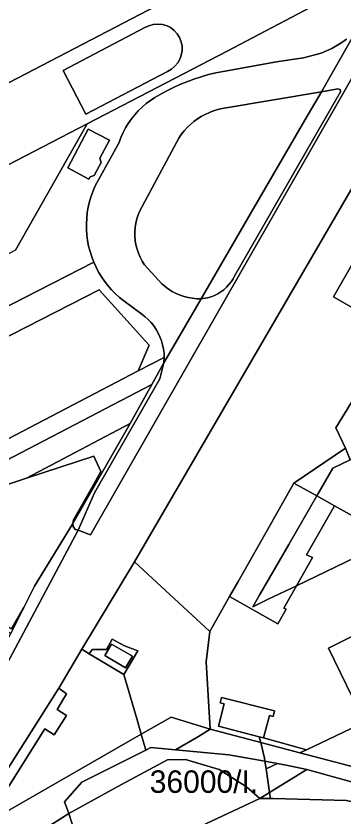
# Model space of a CAD drawing. Extents: x -537068 to -534056, y -1176840 to -1172401.
# Drawn here: x -536084.1 to -536011, y -1175324.5 to -1175146.2 of the extents above; entities that cross this region are included whole.
import ezdxf

# ---------------------------------------------------------------- set-up
doc = ezdxf.new("R2010")
doc.units = 0
for name, color, linetype in [('95560013', 7, 'Continuous'), ('95590013', 7, 'Continuous'), ('95630013', 7, 'Continuous'), ('95640013', 7, 'Continuous'), ('95660013', 7, 'Continuous')]:
    doc.layers.add(name, color=color, linetype=linetype)

msp = doc.modelspace()

# ---------------------------------------------------------------- linework, layer by layer
at = {"layer": '95560013'}
for points in [[(-536054.62, -1175144.91), (-536125.64, -1175181.74), (-536189.92, -1175215.07), (-536156.5, -1175178.11), (-536127.83, -1175145.22), (-536061.58, -1175110.73), (-535994.48, -1175074.73), (-535960.11, -1175056.29), (-535953.43, -1175065.31), (-535960.73, -1175075.89), (-535971.74, -1175091.4), (-535983.6, -1175108.09)], [(-536178.93, -1175228.66), (-536210.17, -1175250.41), (-536219.68, -1175249.12), (-536204.88, -1175232.04), (-536189.92, -1175215.07), (-536125.64, -1175181.74), (-536054.62, -1175144.91), (-535983.6, -1175108.09), (-535999.49, -1175133.94), (-535999.76, -1175134.32), (-536037.06, -1175154.03), (-536068.2, -1175170.14), (-536103.53, -1175188.42)], [(-536050.43, -1175148.4), (-536051.48, -1175148.08), (-536052.53, -1175147.97), (-536053.55, -1175148.06), (-536054.52, -1175148.33), (-536055.42, -1175148.77), (-536073.61, -1175158.31), (-536068.5, -1175168.05), (-536050.34, -1175158.5), (-536049.47, -1175158.01), (-536048.69, -1175157.37), (-536048.03, -1175156.58), (-536047.52, -1175155.66), (-536047.19, -1175154.62), (-536047.09, -1175153.91), (-536047.1, -1175152.89), (-536047.3, -1175151.9), (-536047.67, -1175150.97), (-536048.2, -1175150.12), (-536048.89, -1175149.38), (-536049.71, -1175148.77)]]:
    msp.add_lwpolyline(points, close=True, dxfattribs=at)
at = {"layer": '95590013'}
for points in [[(-536084.19, -1175198.31), (-536068.2, -1175170.14), (-536037.06, -1175154.03), (-535999.76, -1175134.32)], [(-536010.49, -1175151.32), (-536011.55, -1175152.07), (-536012.64, -1175152.76), (-536013.78, -1175153.39), (-536014.94, -1175153.95), (-536016.14, -1175154.44), (-536020.08, -1175155.46), (-536026.06, -1175156.41), (-536037.95, -1175158.5), (-536039.6, -1175158.84), (-536041.24, -1175159.23), (-536042.86, -1175159.69), (-536044.47, -1175160.22), (-536046.05, -1175160.8), (-536047.61, -1175161.44), (-536049.15, -1175162.13), (-536050.65, -1175162.89), (-536052.13, -1175163.7), (-536053.16, -1175164.29), (-536054.15, -1175164.95), (-536055.1, -1175165.67), (-536056, -1175166.45), (-536056.85, -1175167.28), (-536057.65, -1175168.16), (-536058.39, -1175169.09), (-536059.07, -1175170.07), (-536059.69, -1175171.09), (-536060.24, -1175172.14), (-536060.72, -1175173.23), (-536061.14, -1175174.34), (-536066.42, -1175183.96), (-536066.92, -1175185.11), (-536067.35, -1175186.28), (-536067.7, -1175187.48), (-536067.99, -1175188.7), (-536068.2, -1175189.93), (-536068.34, -1175191.17), (-536068.4, -1175192.42), (-536068.39, -1175193.67), (-536068.3, -1175194.92), (-536068.14, -1175196.16), (-536067.91, -1175197.39), (-536067.6, -1175198.6), (-536067.22, -1175199.79), (-536066.77, -1175200.96), (-536100.61, -1175218.24)], [(-536100.61, -1175218.24), (-536066.77, -1175200.96), (-536066.26, -1175202.08), (-536065.69, -1175203.16), (-536065.05, -1175204.21), (-536064.36, -1175205.22), (-536063.6, -1175206.19), (-536062.79, -1175207.11), (-536061.93, -1175207.99), (-536061.02, -1175208.81), (-536060.06, -1175209.57), (-536056.07, -1175212.52), (-536055.33, -1175213.1), (-536054.64, -1175213.73), (-536053.99, -1175214.42), (-536053.41, -1175215.15), (-536052.88, -1175215.93), (-536052.42, -1175216.75), (-536052.02, -1175217.6), (-536051.69, -1175218.48), (-536051.43, -1175219.38), (-536051.24, -1175220.3), (-536051.12, -1175221.23), (-536051.08, -1175222.17), (-536056.87, -1175225.18), (-536054.45, -1175219.42), (-536055.23, -1175218.56), (-536065.59, -1175207.09), (-536098, -1175223.64)]]:
    msp.add_lwpolyline(points, dxfattribs=at)
for points in [[(-536051.6, -1175205.78), (-536055.47, -1175201.53), (-536055.99, -1175200.71), (-536056.44, -1175199.85), (-536056.82, -1175198.96), (-536057.13, -1175198.04), (-536057.36, -1175197.1), (-536057.52, -1175196.14), (-536057.6, -1175195.18), (-536057.61, -1175194.21), (-536057.53, -1175193.24), (-536057.38, -1175192.28), (-536057.16, -1175191.34), (-536056.85, -1175190.42), (-536056.48, -1175189.52), (-536047.84, -1175173.38), (-536047.27, -1175172.55), (-536046.65, -1175171.76), (-536045.97, -1175171.02), (-536045.25, -1175170.32), (-536044.48, -1175169.68), (-536043.67, -1175169.09), (-536042.82, -1175168.55), (-536041.94, -1175168.07), (-536041.02, -1175167.66), (-536040.08, -1175167.3), (-536039.12, -1175167.01), (-536038.14, -1175166.79), (-536016.03, -1175163.03), (-536019.73, -1175169.37), (-536031.7, -1175189.91), (-536042.87, -1175209.12), (-536043.83, -1175209.1), (-536044.78, -1175209.01), (-536045.73, -1175208.85), (-536046.65, -1175208.61), (-536047.56, -1175208.3), (-536048.44, -1175207.93), (-536049.29, -1175207.48), (-536050.1, -1175206.98), (-536050.88, -1175206.41)], [(-536084.19, -1175198.31), (-536104.99, -1175209.19), (-536164.36, -1175240.23), (-536192.84, -1175260.15), (-536195.67, -1175258.06), (-536205.32, -1175260.27), (-536214.58, -1175253.88), (-536210.17, -1175250.41), (-536178.93, -1175228.66), (-536103.53, -1175188.42), (-536068.2, -1175170.14)], [(-536067.86, -1175182.48), (-536067.59, -1175181.97), (-536066.67, -1175181.69), (-536065.12, -1175178.78), (-536065.41, -1175177.84), (-536063.28, -1175173.81), (-536067.98, -1175171.33), (-536072.56, -1175180)], [(-536096.17, -1175227.42), (-536098, -1175223.64), (-536065.59, -1175207.09), (-536055.23, -1175218.56), (-536054.45, -1175219.42), (-536056.87, -1175225.18), (-536089.15, -1175241.96), (-536091.37, -1175237.36), (-536093.77, -1175232.39)], [(-536051.08, -1175222.17), (-536051.13, -1175223.39), (-536053.84, -1175228.22), (-536086.44, -1175245.15), (-536100.79, -1175252.85), (-536124.04, -1175266.29), (-536137.58, -1175274.39), (-536150.6, -1175283.46), (-536154.77, -1175279.13), (-536124.94, -1175260.56), (-536089.15, -1175241.96), (-536056.87, -1175225.18)], [(-536095.46, -1175253.58), (-536097.74, -1175257.55), (-536117.45, -1175267.99), (-536147, -1175287.2), (-536150.6, -1175283.46), (-536137.58, -1175274.39), (-536124.04, -1175266.29), (-536100.79, -1175252.85), (-536086.44, -1175245.15), (-536053.84, -1175228.22), (-536058.69, -1175236.86), (-536081.73, -1175249.07)], [(-536081.73, -1175249.07), (-536058.69, -1175236.86), (-536066.56, -1175250.59), (-536067.07, -1175250.88), (-536065.21, -1175247.58), (-536066.72, -1175244.13)], [(-536067.07, -1175250.88), (-536066.56, -1175250.59), (-536071.45, -1175259.11), (-536071.27, -1175258.29)], [(-536051.03, -1175330.31), (-536052.39, -1175326.63), (-536069.36, -1175333.07), (-536070.72, -1175328.8), (-536072.32, -1175323.69), (-536060.56, -1175317.19), (-536050.36, -1175311.71), (-536046.36, -1175311.63), (-536038.85, -1175313.85), (-536032.73, -1175317.76), (-536029.77, -1175320.33)]]:
    msp.add_lwpolyline(points, close=True, dxfattribs=at)
at = {"layer": '95630013'}
for points in [[(-536056.18, -1175306.04), (-536049.5, -1175302.21), (-536040.85, -1175304.92), (-536043.42, -1175306.54), (-536048.56, -1175309.47), (-536054.03, -1175308.96), (-536055.2, -1175309.55)], [(-536028.73, -1175311.35), (-536028.63, -1175312.06), (-536036.71, -1175310.59), (-536048.56, -1175309.47), (-536043.42, -1175306.54), (-536040.85, -1175304.92), (-536029.59, -1175307.87)], [(-536073.25, -1175321.08), (-536072.32, -1175323.69), (-536082.9, -1175330.42), (-536089.72, -1175333.91), (-536093.25, -1175335.47), (-536096.47, -1175336.83), (-536098.11, -1175337.72), (-536096.43, -1175335), (-536093.75, -1175330.67), (-536092.69, -1175328.97), (-536090.76, -1175325.85), (-536056.18, -1175306.04), (-536055.2, -1175309.55), (-536069.41, -1175316.73)], [(-536028.39, -1175313.76), (-536027.63, -1175319.02), (-536029.77, -1175320.33), (-536032.73, -1175317.76), (-536038.85, -1175313.85), (-536046.36, -1175311.63), (-536050.36, -1175311.71), (-536060.56, -1175317.19), (-536072.32, -1175323.69), (-536073.25, -1175321.08), (-536069.41, -1175316.73), (-536055.2, -1175309.55), (-536054.03, -1175308.96), (-536048.56, -1175309.47), (-536036.71, -1175310.59), (-536028.63, -1175312.06)], [(-536029.77, -1175320.33), (-536027.63, -1175319.02), (-536027.44, -1175320.35)]]:
    msp.add_lwpolyline(points, close=True, dxfattribs=at)
at = {"layer": '95640013'}
for points in [[(-536006.58, -1175180), (-536057.72, -1175267.69), (-536069.4, -1175287.13), (-536074.57, -1175295.75), (-536092.07, -1175323.29), (-536092.88, -1175324.61), (-536095.32, -1175328.57), (-536096.89, -1175328.33), (-536105.95, -1175326.95), (-536107.53, -1175326.71), (-536108.93, -1175324.45), (-536106.79, -1175321.11), (-536105.14, -1175318.55), (-536092.78, -1175302.83), (-536070.22, -1175260.64), (-536067.46, -1175261.62), (-535997.55, -1175139.48)], [(-535997.55, -1175139.48), (-536067.46, -1175261.62), (-536070.22, -1175260.64), (-536066.61, -1175252.27), (-536052.02, -1175226.9), (-536051.13, -1175223.39), (-536050.19, -1175221.71), (-536046.27, -1175214.97), (-536042.87, -1175209.12), (-536041.42, -1175208.89), (-536040.64, -1175208.66), (-536039.88, -1175208.37), (-536039.16, -1175208.01), (-536038.46, -1175207.58), (-536037.81, -1175207.1), (-536037.2, -1175206.56), (-536036.65, -1175205.97), (-536036.15, -1175205.33), (-536035.7, -1175204.65), (-536035.32, -1175203.93), (-536011.78, -1175163.05), (-536011.91, -1175162.56), (-536012.39, -1175162.41), (-536016.03, -1175163.03), (-536015.73, -1175162.52), (-536008.33, -1175149.45)], [(-536008.33, -1175149.45), (-536015.73, -1175162.52), (-536016.03, -1175163.03), (-536038.14, -1175166.79), (-536039.12, -1175167.01), (-536040.08, -1175167.3), (-536041.02, -1175167.66), (-536041.94, -1175168.07), (-536042.82, -1175168.55), (-536043.67, -1175169.09), (-536044.48, -1175169.68), (-536045.25, -1175170.32), (-536045.97, -1175171.02), (-536046.65, -1175171.76), (-536047.27, -1175172.55), (-536047.84, -1175173.38), (-536056.48, -1175189.52), (-536056.85, -1175190.42), (-536057.16, -1175191.34), (-536057.38, -1175192.28), (-536057.53, -1175193.24), (-536057.61, -1175194.21), (-536057.6, -1175195.18), (-536057.52, -1175196.14), (-536057.36, -1175197.1), (-536057.13, -1175198.04), (-536056.82, -1175198.96), (-536056.44, -1175199.85), (-536055.99, -1175200.71), (-536055.47, -1175201.53), (-536051.6, -1175205.78), (-536050.88, -1175206.41), (-536050.1, -1175206.98), (-536049.29, -1175207.48), (-536048.44, -1175207.93), (-536047.56, -1175208.3), (-536046.65, -1175208.61), (-536045.73, -1175208.85), (-536044.78, -1175209.01), (-536043.83, -1175209.1), (-536042.87, -1175209.12), (-536046.27, -1175214.97), (-536050.19, -1175221.71), (-536051.13, -1175223.39), (-536051.08, -1175222.17), (-536051.12, -1175221.23), (-536051.24, -1175220.3), (-536051.43, -1175219.38), (-536051.69, -1175218.48), (-536052.02, -1175217.6), (-536052.42, -1175216.75), (-536052.88, -1175215.93), (-536053.41, -1175215.15), (-536053.99, -1175214.42), (-536054.64, -1175213.73), (-536055.33, -1175213.1), (-536056.07, -1175212.52), (-536060.06, -1175209.57), (-536061.02, -1175208.81), (-536061.93, -1175207.99), (-536062.79, -1175207.11), (-536063.6, -1175206.19), (-536064.36, -1175205.22), (-536065.05, -1175204.21), (-536065.69, -1175203.16), (-536066.26, -1175202.08), (-536066.77, -1175200.96), (-536067.22, -1175199.79), (-536067.6, -1175198.6), (-536067.91, -1175197.39), (-536068.14, -1175196.16), (-536068.3, -1175194.92), (-536068.39, -1175193.67), (-536068.4, -1175192.42), (-536068.34, -1175191.17), (-536068.2, -1175189.93), (-536067.99, -1175188.7), (-536067.7, -1175187.48), (-536067.35, -1175186.28), (-536066.92, -1175185.11), (-536066.42, -1175183.96), (-536061.14, -1175174.34), (-536060.72, -1175173.23), (-536060.24, -1175172.14), (-536059.69, -1175171.09), (-536059.07, -1175170.07), (-536058.39, -1175169.09), (-536057.65, -1175168.16), (-536056.85, -1175167.28), (-536056, -1175166.45), (-536055.1, -1175165.67), (-536054.15, -1175164.95), (-536053.16, -1175164.29), (-536052.13, -1175163.7), (-536050.65, -1175162.89), (-536049.15, -1175162.13), (-536047.61, -1175161.44), (-536046.05, -1175160.8), (-536044.47, -1175160.22), (-536042.86, -1175159.69), (-536041.24, -1175159.23), (-536039.6, -1175158.84), (-536037.95, -1175158.5), (-536026.06, -1175156.41), (-536020.08, -1175155.46), (-536016.14, -1175154.44), (-536014.94, -1175153.95), (-536013.78, -1175153.39), (-536012.64, -1175152.76), (-536011.55, -1175152.07), (-536010.49, -1175151.32)], [(-536003.42, -1175222.5), (-536012.83, -1175237.86), (-536010.73, -1175242.37), (-536022.18, -1175250.17), (-536028.36, -1175261.04), (-536034.68, -1175272.17), (-536036.5, -1175275.39), (-536040.89, -1175283.14), (-536057.72, -1175267.69), (-536006.58, -1175180)], [(-536003.09, -1175190.79), (-536013.4, -1175208.69), (-536006.52, -1175212.63)], [(-535960.29, -1175259.84), (-536014.5, -1175286.88), (-536006.45, -1175303.32), (-536019.38, -1175309.48), (-536028.93, -1175306.85), (-536027.66, -1175301.85), (-536026.79, -1175302.07), (-536026.48, -1175300.86), (-536038.33, -1175297.84), (-536038.63, -1175299.06), (-536037.76, -1175299.28), (-536038.99, -1175304.24), (-536029.9, -1175306.6), (-536029.59, -1175307.87), (-536040.85, -1175304.92), (-536041.7, -1175289.93), (-536040.89, -1175283.14), (-536036.5, -1175275.39), (-536025.76, -1175281.46), (-536023.94, -1175278.23), (-536024.46, -1175277.94), (-536021.64, -1175272.99), (-535999.92, -1175262.53)]]:
    msp.add_lwpolyline(points, dxfattribs=at)
for points in [[(-536073.61, -1175158.31), (-536055.42, -1175148.77), (-536054.52, -1175148.33), (-536053.55, -1175148.06), (-536052.53, -1175147.97), (-536051.48, -1175148.08), (-536050.43, -1175148.4), (-536049.71, -1175148.77), (-536048.89, -1175149.38), (-536048.2, -1175150.12), (-536047.67, -1175150.97), (-536047.3, -1175151.9), (-536047.1, -1175152.89), (-536047.09, -1175153.91), (-536047.19, -1175154.62), (-536047.52, -1175155.66), (-536048.03, -1175156.58), (-536048.69, -1175157.37), (-536049.47, -1175158.01), (-536050.34, -1175158.5), (-536068.5, -1175168.05)], [(-536031.7, -1175189.91), (-536019.73, -1175169.37), (-536016.03, -1175163.03), (-536012.39, -1175162.41), (-536011.91, -1175162.56), (-536011.78, -1175163.05), (-536035.32, -1175203.93), (-536035.7, -1175204.65), (-536036.15, -1175205.33), (-536036.65, -1175205.97), (-536037.2, -1175206.56), (-536037.81, -1175207.1), (-536038.46, -1175207.58), (-536039.16, -1175208.01), (-536039.88, -1175208.37), (-536040.64, -1175208.66), (-536041.42, -1175208.89), (-536042.87, -1175209.12)], [(-536065.12, -1175178.78), (-536066.67, -1175181.69), (-536067.59, -1175181.97), (-536067.86, -1175182.48), (-536072.56, -1175180), (-536067.98, -1175171.33), (-536063.28, -1175173.81), (-536065.41, -1175177.84)], [(-536003.09, -1175190.79), (-535996.3, -1175194.76), (-535994.52, -1175195.86), (-535991.02, -1175189.7), (-535978.79, -1175196.8), (-535970.96, -1175202.13), (-535968.03, -1175207.99), (-535964.85, -1175215.84), (-535961.82, -1175221.41), (-535963.9, -1175222.62), (-535992.6, -1175236.67), (-535994.16, -1175237.43), (-536005.74, -1175243.07), (-536009.65, -1175244.97), (-536010.73, -1175242.37), (-536012.83, -1175237.86), (-536003.42, -1175222.5), (-536004.88, -1175221.68), (-536004.08, -1175220.35), (-536007.44, -1175218.43), (-536004.74, -1175213.65), (-536006.52, -1175212.63), (-536013.4, -1175208.69)], [(-536071.32, -1175259.8), (-536071.45, -1175259.11), (-536066.56, -1175250.59), (-536058.69, -1175236.86), (-536053.84, -1175228.22), (-536051.13, -1175223.39), (-536052.02, -1175226.9), (-536066.61, -1175252.27), (-536070.22, -1175260.64), (-536070.88, -1175260.44)], [(-536022.18, -1175250.17), (-536010.73, -1175242.37), (-536009.65, -1175244.97), (-536013.49, -1175246.79), (-536017.08, -1175253)], [(-536003.46, -1175247.73), (-536004.27, -1175248.13), (-536003.73, -1175249.21), (-535991.44, -1175243.05), (-535985.32, -1175255.53), (-535982.41, -1175261.57), (-535992.56, -1175266.62), (-535999.92, -1175262.53), (-536013.12, -1175255.2), (-536017.08, -1175253), (-536013.49, -1175246.79), (-536009.65, -1175244.97), (-536005.74, -1175243.07), (-536005.65, -1175243.25)], [(-536081.73, -1175249.07), (-536066.72, -1175244.13), (-536065.21, -1175247.58), (-536067.07, -1175250.88), (-536071.27, -1175258.29), (-536071.45, -1175259.11), (-536072.44, -1175260.84), (-536079.94, -1175273.05), (-536082.34, -1175277.81), (-536085.06, -1175282.61), (-536098.94, -1175274.82), (-536104.15, -1175271.89), (-536108.34, -1175269.54), (-536103.41, -1175260.78), (-536100.55, -1175262.46), (-536100.03, -1175261.54), (-536097.74, -1175257.55), (-536095.46, -1175253.58)], [(-536036.5, -1175275.39), (-536034.68, -1175272.17), (-536028.36, -1175261.04), (-536022.18, -1175250.17), (-536017.08, -1175253), (-536023.35, -1175263.84), (-536029.77, -1175274.94), (-536031.35, -1175277.67), (-536027.89, -1175276), (-536021.64, -1175272.99), (-536024.46, -1175277.94), (-536023.94, -1175278.23), (-536025.76, -1175281.46)], [(-536027.89, -1175276), (-536031.35, -1175277.67), (-536029.77, -1175274.94), (-536023.35, -1175263.84), (-536017.08, -1175253), (-536013.12, -1175255.2), (-536019.37, -1175266.07), (-536018.07, -1175266.72), (-536021.64, -1175272.99)], [(-536021.64, -1175272.99), (-536018.07, -1175266.72), (-536019.37, -1175266.07), (-536013.12, -1175255.2), (-535999.92, -1175262.53)], [(-536092.78, -1175302.83), (-536105.14, -1175318.55), (-536106.79, -1175321.11), (-536108.93, -1175324.45), (-536111.06, -1175320.99), (-536096.32, -1175297.69), (-536088.03, -1175288.6), (-536085.27, -1175283.61), (-536082.34, -1175277.81), (-536079.94, -1175273.05), (-536072.44, -1175260.84), (-536071.45, -1175259.11), (-536071.32, -1175259.8), (-536070.88, -1175260.44), (-536070.22, -1175260.64)], [(-536006.45, -1175303.32), (-536014.5, -1175286.88), (-535960.29, -1175259.84), (-535952.21, -1175276.13), (-536001.03, -1175300.63), (-536003.83, -1175302.02)], [(-536060.04, -1175292.74), (-536056.96, -1175287.5), (-536059.92, -1175286.35), (-536062.66, -1175284.89), (-536063.95, -1175287.2), (-536067.11, -1175287.21), (-536067.77, -1175288.11), (-536069.4, -1175287.13), (-536057.72, -1175267.69), (-536040.89, -1175283.14), (-536041.7, -1175289.93), (-536040.85, -1175304.92), (-536049.5, -1175302.21), (-536056.18, -1175306.04), (-536057.08, -1175302.83)], [(-536085.27, -1175283.61), (-536088.03, -1175282.06), (-536090.88, -1175287.02), (-536098.08, -1175283.3), (-536107.34, -1175278), (-536104.81, -1175277.91), (-536098.94, -1175274.82), (-536085.06, -1175282.61), (-536082.34, -1175277.81)], [(-536062.66, -1175284.89), (-536059.92, -1175286.35), (-536056.96, -1175287.5), (-536060.04, -1175292.74), (-536067.77, -1175288.11), (-536067.11, -1175287.21), (-536063.95, -1175287.2)], [(-536064.33, -1175288.53), (-536062.8, -1175285.97), (-536058.15, -1175288.67), (-536059.69, -1175291.22)], [(-536064.33, -1175288.53), (-536059.69, -1175291.22), (-536058.15, -1175288.67), (-536062.8, -1175285.97)], [(-536075.57, -1175306.14), (-536072.85, -1175301.86), (-536074.95, -1175300.55), (-536072.86, -1175297.04), (-536074.57, -1175295.75), (-536069.4, -1175287.13), (-536067.77, -1175288.11), (-536060.04, -1175292.74), (-536057.08, -1175302.83), (-536056.18, -1175306.04), (-536090.76, -1175325.85), (-536087.18, -1175319.93), (-536077.66, -1175304.81)], [(-536090.76, -1175325.85), (-536092.88, -1175324.61), (-536092.07, -1175323.29), (-536074.57, -1175295.75), (-536072.86, -1175297.04), (-536074.95, -1175300.55), (-536072.85, -1175301.86), (-536075.57, -1175306.14), (-536077.66, -1175304.81), (-536087.18, -1175319.93)], [(-536029.9, -1175306.6), (-536038.99, -1175304.24), (-536037.76, -1175299.28), (-536038.63, -1175299.06), (-536038.33, -1175297.84), (-536026.48, -1175300.86), (-536026.79, -1175302.07), (-536027.66, -1175301.85), (-536028.93, -1175306.85)], [(-535986.85, -1175319.09), (-535992.78, -1175317.53), (-536020.84, -1175310.17), (-536019.38, -1175309.48), (-536006.45, -1175303.32), (-536003.83, -1175302.02), (-536002.86, -1175303.98), (-536000.05, -1175302.56), (-535995.48, -1175311.52), (-535994.19, -1175310.88), (-535991, -1175317.28), (-535984.42, -1175317.98)], [(-536029.9, -1175306.6), (-536028.93, -1175306.85), (-536019.38, -1175309.48), (-536020.84, -1175310.17), (-536029.59, -1175307.87)], [(-536029.59, -1175307.87), (-536020.84, -1175310.17), (-535992.78, -1175317.53), (-535996.53, -1175320.17), (-536019.28, -1175313.9), (-536023.15, -1175313.06), (-536025.87, -1175312.56), (-536028.63, -1175312.06), (-536028.73, -1175311.35)], [(-536025.87, -1175312.56), (-536028.39, -1175313.76), (-536028.63, -1175312.06)], [(-536028.39, -1175313.76), (-536025.87, -1175312.56), (-536023.15, -1175313.06), (-536019.28, -1175313.9), (-536027.63, -1175319.02)], [(-536019.28, -1175313.9), (-535996.53, -1175320.17), (-536000.7, -1175323.1), (-536010.49, -1175320.81), (-536026.78, -1175320.35), (-536027.44, -1175320.35), (-536027.63, -1175319.02)], [(-536029.77, -1175320.33), (-536027.44, -1175320.35), (-536026.78, -1175320.35), (-536010.49, -1175320.81), (-536000.7, -1175323.1), (-535988.06, -1175326.06), (-535988.25, -1175328.5), (-536002.33, -1175332.52), (-536018.23, -1175337.25), (-536026.63, -1175339.73), (-536026.8, -1175339.78), (-536030.67, -1175328.42), (-536048.17, -1175336.56), (-536050.74, -1175331.13), (-536051.03, -1175330.31)], [(-536062.61, -1175350.5), (-536075.74, -1175354.33), (-536076.7, -1175349.98), (-536078.02, -1175344.85), (-536080.45, -1175337.2), (-536081.75, -1175333.26), (-536082.9, -1175330.42), (-536072.32, -1175323.69), (-536070.72, -1175328.8), (-536069.36, -1175333.07), (-536067.7, -1175337.7), (-536067.1, -1175339.36), (-536064.11, -1175346.07)]]:
    msp.add_lwpolyline(points, close=True, dxfattribs=at)

# ---------------------------------------------------------------- texts
at = {"layer": '95660013'}
msp.add_text('36000/I.', height=5, rotation=0, dxfattribs=at).set_placement((-536054.3, -1175319.08))

doc.saveas('drawing.dxf')
